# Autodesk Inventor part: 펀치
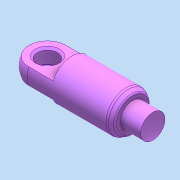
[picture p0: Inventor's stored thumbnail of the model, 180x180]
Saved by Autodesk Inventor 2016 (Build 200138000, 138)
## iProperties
Created: 2024-08
Part Number: 펀치
Material: 일반
Document SubType Name: Modeling
Designer: pc-7
Density: 1 g/cm^3
Appearance: 기본값
Author: jhkim
Sending System: Autodesk Inventor 2025
Preprocessor: ST-DEVELOPER v20
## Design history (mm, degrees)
node "펀치1"
node "솔리드2"
node "솔리드1"
